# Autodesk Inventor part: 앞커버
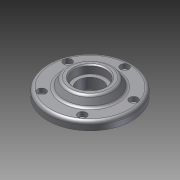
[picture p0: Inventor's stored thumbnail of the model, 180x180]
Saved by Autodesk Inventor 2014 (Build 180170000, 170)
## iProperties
Company: 한국ATC센터
Created: 2014-03
Part Number: 앞커버
Document SubType Name: Modeling
Designer: KYOUNG IL JANG
Density: 1 g/cm^3
Material: 일반
Appearance: 기본값
Author: KYOUNG IL JANG
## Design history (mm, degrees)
sketch "스케치1"
  geometry: C1 r 26 at (0, 0); C2 r 40 at (0, 0); 1 further point
  constraints: 2 centre point, 2 coincident
  dimensions: "d0" = 52 diameter of C1; "d1" = 80 diameter of C2
extrude "돌출1" new body sketch "스케치1" distance "d2" = 8; taper "d3" = 0 deg
extrude "돌출2" join sketch "스케치1" distance "d4" = 5; taper "d5" = 0 deg
sketch "스케치2"
  geometry: C1 r 25 at (0, 0); 1 further point
  constraints: 1 centre point, 1 coincident
  dimensions: "d6" = 50 diameter of C1
extrude "돌출3" join sketch "스케치2" distance "d7" = 8; taper "d8" = -30 deg
sketch "스케치3"
  geometry: C1 r 1.729 at (0, 33) reference; 1 further point
hole "구멍1" sketch "스케치3" at (0, 33) diameter "d9" = 4.5; stored, may be unused: countersink angle "d13" = 90 deg, drill point angle "d15" = 118 deg; dims "d10" = 6, "d11" = 8, "d12" = 4.4, "d14" = 8
hole "구멍2" diameter "d21" = 23; stored, may be unused: countersink angle "d25" = 90 deg, drill point angle "d27" = 118 deg; dims "d19" = 10, "d20" = 10, "d22" = 6, "d23" = 30, "d24" = 8, "d26" = 8
fillet "모깎기1" dims "d28" = 3, "d29" = 0.3
hole "구멍3" diameter "d32" = 40; stored, may be unused: countersink angle "d36" = 90 deg, drill point angle "d38" = 0 deg; dims "d30" = 10, "d31" = 10, "d33" = 6, "d34" = 30, "d35" = 8, "d37" = 3
fillet "모깎기2" dims "d39" = 3
chamfer "모따기1" distance "d40" = 1; stored, may be unused: second distance "d41" = 2, angle "d42" = 45 deg
node "솔리드1"
pattern_circular "원형 패턴1" dims angle "d17" = 360 deg
node "참조1"
